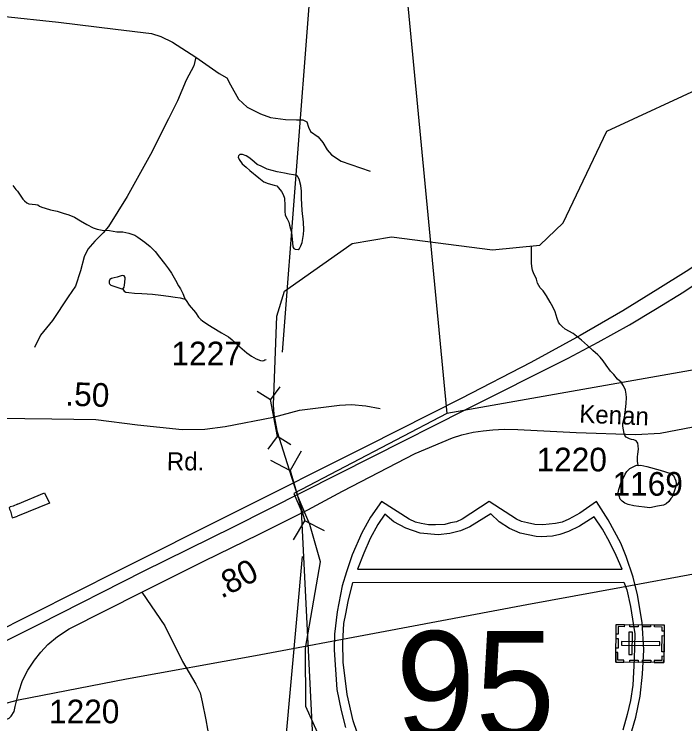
# Model space of a CAD drawing. Extents: x 2082433 to 2279600, y 546599 to 755198.
# Drawn here: x 2149060 to 2152603, y 600142 to 603893 of the extents above; entities that cross this region are included whole.
import ezdxf

# ---------------------------------------------------------------- set-up
doc = ezdxf.new("R2010")
doc.units = 0
for name, color, linetype in [('Exist Boundary Political Fire Districts', 7, 'Continuous'), ('Exist Cultural Cemetery CELL', 7, 'Continuous'), ('Exist Hydrographic Creek Single Shore', 7, 'Continuous'), ('Exist Hydrographic Misc Water Feature', 7, 'Continuous'), ('Exist Hydrographic Pond Under 1500 Sq Ft', 7, 'Continuous'), ('Exist Road Non-System Type 51', 7, 'Continuous'), ('Exist Road Primary Interstate Divided Center Attributed', 7, 'Continuous'), ('Exist Road Primary Interstate Shield CELL', 7, 'Continuous'), ('Exist Road Primary Interstate Shield Number Label', 7, 'Continuous'), ('Exist Road Primary Interstate Structure Culvert CELL', 7, 'Continuous'), ('Exist Road Primary Interstate Structure Culvert Number Label', 7, 'Continuous'), ('Exist Road Secondary Mileage Hundredths English Label', 7, 'Continuous'), ('Exist Road Secondary Structure Culvert CELL', 7, 'Continuous'), ('Exist Road Secondary Structure Standard Bridge Number Label', 7, 'Continuous'), ('Exist Road Secondary Type 51 Attributed', 7, 'Continuous'), ('Exist Road Secondary Type 51 Label', 7, 'Continuous'), ('Exist Road Secondary Type 51 Number Label', 7, 'Continuous'), ('Exist Utilities Electrical Transmission Line', 7, 'Continuous')]:
    doc.layers.add(name, color=color, linetype=linetype)

msp = doc.modelspace()

# ---------------------------------------------------------------- linework, layer by layer
at = {"layer": 'Exist Boundary Political Fire Districts'}
for points in [[(2150227.4, 608573.5), (2150803.4, 607458.3), (2151346, 601782.1)], [(2159905.3, 603293.7), (2151346, 601782.1)], [(2151346, 601782.1), (2150536.8, 601359.3), (2150575.6, 601269.6), (2150804, 596727.4), (2150538.7, 590463.1), (2150181.1, 589645.7), (2149537.2, 589006.2), (2148987.7, 588267)]]:
    msp.add_lwpolyline(points, dxfattribs=at)
at = {"layer": 'Exist Cultural Cemetery CELL'}
for points in [[(2152238.3, 600467.9), (2152240.1, 600667), (2152494.7, 600664.7), (2152492.9, 600465.6)], [(2152283.5, 600666.7), (2152283.4, 600655.3), (2152251.2, 600655.6), (2152250.8, 600615.1), (2152239.7, 600615.2), (2152240.2, 600667.1)], [(2152356.5, 600654.6), (2152313.1, 600655), (2152313.2, 600666.4), (2152356.6, 600666)], [(2152422.4, 600654), (2152379.1, 600654.4), (2152379.2, 600665.7), (2152422.5, 600665.4)], [(2152494.4, 600631.5), (2152483, 600631.6), (2152483.2, 600653.6), (2152442.7, 600654), (2152442.8, 600665.1), (2152494.7, 600664.7)], [(2152306.7, 600508.1), (2152325.4, 600507.9), (2152326.5, 600625.7), (2152307.8, 600625.9)], [(2152482, 600523.2), (2152482.7, 600608), (2152494.1, 600607.9), (2152493.4, 600523)], [(2152239, 600542), (2152239.5, 600593.8), (2152250.9, 600593.7), (2152250.4, 600541.9)], [(2152268.6, 600576.7), (2152268.4, 600558), (2152471.2, 600556.1), (2152471.4, 600574.8)], [(2152281.6, 600467.5), (2152281.7, 600478.9), (2152249.5, 600479.2), (2152249.9, 600519.7), (2152238.8, 600519.8), (2152238.3, 600467.9)], [(2152493.2, 600498.7), (2152481.7, 600498.8), (2152481.5, 600476.8), (2152441.1, 600477.1), (2152441, 600466), (2152492.9, 600465.5)], [(2152355.8, 600466.8), (2152312.4, 600467.2), (2152312.6, 600478.6), (2152355.9, 600478.2)], [(2152423, 600466.2), (2152379.7, 600466.6), (2152379.8, 600478), (2152423.1, 600477.6)]]:
    msp.add_lwpolyline(points, close=True, dxfattribs=at)
at = {"layer": 'Exist Hydrographic Creek Single Shore'}
for points in [[(2150737.1, 599557.9), (2150812.2, 599625.3), (2150811.2, 599766.4), (2150600.2, 600233.2), (2150599.1, 600541.6), (2150679.1, 600999.1), (2150621.9, 601196.4), (2150595.1, 601256.7), (2150558.2, 601345.6), (2150514.5, 601483.1), (2150451, 601683.5), (2150434.2, 601777.4), (2150430.8, 601828.1), (2150447.2, 602296.3), (2150488.2, 602430), (2150845.2, 602681.9), (2151053.1, 602717.1), (2151586.3, 602647.2), (2151836.2, 602671.7), (2151960.3, 602790.6), (2152191.2, 603274.7), (2152731.3, 603526.1)], [(2152357.1, 601507.5), (2152352.8, 601531.2), (2152353, 601539.3), (2152352.8, 601553.6), (2152354.6, 601567.4), (2152358.5, 601593.2), (2152356.5, 601611.4), (2152354.2, 601625.5), (2152350.5, 601631.4), (2152346.2, 601637.3), (2152334.1, 601643.2), (2152322.2, 601645.4), (2152310.1, 601649.2), (2152300.1, 601653.2), (2152292.3, 601657.2), (2152286.1, 601667), (2152282, 601677), (2152275.9, 601714.8), (2152275.7, 601729), (2152281.6, 601748.8), (2152285.5, 601773), (2152289.2, 601802.8), (2152292.9, 601835.1), (2152294.9, 601866.9), (2152292.7, 601885), (2152288.8, 601906.7), (2152278.3, 601929), (2152266.4, 601948.6), (2152248.2, 601964.7), (2152228.5, 601988.4), (2152210.3, 602006.6), (2152188.3, 602038.3), (2152171.5, 602060.3), (2152155.7, 602080.1), (2152143.6, 602092.1), (2152117.4, 602115.9), (2152089.5, 602141.6), (2152057.1, 602169.6), (2152031.5, 602191.4), (2152012.8, 602205.2), (2151971, 602228.9), (2151954.6, 602242.7), (2151942.9, 602254.6), (2151936.5, 602264.9), (2151928.7, 602284.8), (2151918.7, 602320.8), (2151906.4, 602346.5), (2151892, 602370.6), (2151872.3, 602404.4), (2151854.1, 602430.3), (2151839.7, 602446.3), (2151831.7, 602460), (2151825.6, 602471.9), (2151819.6, 602491.9), (2151815.3, 602501.9), (2151805.3, 602520), (2151799.1, 602540), (2151795.2, 602560.1), (2151793, 602579.8), (2151792.2, 602667.4)]]:
    msp.add_lwpolyline(points, dxfattribs=at)
at = {"layer": 'Exist Hydrographic Misc Water Feature'}
for points in [[(2150304.5, 603067.3), (2150353.1, 603027.5), (2150378.7, 603007.8), (2150401.3, 602997.9), (2150433.3, 602990.3), (2150447, 602986.2), (2150457.3, 602976.1), (2150473.1, 602956.3), (2150481.5, 602940.4), (2150487.4, 602920.4), (2150489.7, 602882.3), (2150489.9, 602850.3), (2150491.9, 602832.5), (2150494, 602826.6), (2150502.2, 602812.3), (2150510.4, 602794.5), (2150514.5, 602778.4), (2150524.3, 602738.8), (2150530.7, 602686.8), (2150532.9, 602662.9), (2150537.2, 602654.9), (2150545, 602650.9), (2150560.8, 602648.9), (2150567, 602654.9), (2150574.8, 602669.1), (2150580.7, 602686.9), (2150588.7, 602729.1), (2150590.6, 602753.2), (2150588.3, 602793.2), (2150581.9, 602855), (2150577.2, 602921), (2150577.4, 602957.1), (2150575.2, 602987), (2150564.9, 603020.6), (2150559, 603032.9), (2150556.7, 603036.9), (2150552.6, 603040.7), (2150536.6, 603044.7), (2150512.6, 603048.4), (2150488.6, 603052.4), (2150448.7, 603060.1), (2150396.6, 603074.1), (2150364.8, 603089.8), (2150344.3, 603099.4), (2150314.8, 603123.3), (2150300.6, 603135.2), (2150286.1, 603145.1), (2150266.2, 603151), (2150252.2, 603151.1), (2150244.4, 603144.9), (2150244.2, 603136.8), (2150248.7, 603124.8), (2150264.5, 603102.9), (2150285, 603085.2), (2150304.5, 603067.3)], [(2149053.5, 602987.6), (2149069.5, 602966.5)], [(2149069.5, 602966.5), (2149077.5, 602958.4), (2149106, 602914.7), (2149114, 602906.6), (2149126.3, 602896.7), (2149138.2, 602890.9), (2149156, 602889), (2149172.4, 602886.9), (2149184.3, 602885.1), (2149193.9, 602879.2), (2149206.2, 602873.3), (2149224.3, 602867.3), (2149252.4, 602859.4), (2149286.4, 602851.8), (2149318.2, 602841.7), (2149348.6, 602831.9), (2149378.5, 602820.1), (2149410.3, 602800.2), (2149444.7, 602782.4), (2149476.7, 602764.6), (2149498.9, 602756.8), (2149524.5, 602750.9), (2149563, 602749.2), (2149602.8, 602743.5), (2149634.8, 602743.6), (2149665, 602735.8), (2149696.7, 602726), (2149713.1, 602714.3), (2149750.9, 602688.3), (2149779.2, 602664.5), (2149805.6, 602638.6), (2149827.8, 602608.9), (2149854, 602575), (2149875.7, 602546.9), (2149891.9, 602525), (2149912, 602487.5), (2149928.4, 602457.5), (2149938.5, 602441.3), (2149950.6, 602417.6), (2149960.6, 602393.8), (2149962.5, 602389.5)], [(2149633.6, 602440.2), (2149640.5, 602449.9), (2149642.6, 602461.7), (2149646.3, 602493.6), (2149646.3, 602501.7), (2149642, 602509.7), (2149630.1, 602511.9), (2149604.1, 602503.7), (2149588.1, 602499.6), (2149574.3, 602495.6), (2149566.3, 602491.5), (2149564.5, 602487.4), (2149562, 602481.2), (2149562.4, 602477.5), (2149562.6, 602471.4), (2149564.5, 602467.5), (2149570.2, 602461.3), (2149633.6, 602440.2)], [(2149633.6, 602440.2), (2149640.5, 602429.6), (2149650.8, 602424), (2149665, 602421.8), (2149694.9, 602418.2), (2149734.5, 602416.2), (2149790.9, 602412.6), (2149834.7, 602408.7), (2149874.7, 602403.1), (2149910.6, 602397.3), (2149936.9, 602393.3), (2149956.5, 602389.5), (2149962.5, 602389.5)], [(2149962.5, 602389.5), (2149969, 602379.6), (2149985, 602355.6), (2150017.4, 602315.8), (2150033.4, 602291.9), (2150045.5, 602280), (2150055.2, 602272), (2150077.7, 602256.4), (2150105.6, 602238.4), (2150156.1, 602208.9), (2150191.9, 602186.9), (2150212.2, 602171.2), (2150252.2, 602135.2), (2150288.5, 602103.7), (2150314.4, 602085.6), (2150338.5, 602071.8), (2150360.7, 602062), (2150370.5, 602060.1), (2150378.5, 602062.1), (2150384.3, 602066.1), (2150390.6, 602068)], [(2149077.3, 601303.4), (2149220.8, 601363.6), (2149247.3, 601308.1), (2149077.7, 601239.7)], [(2149077.3, 601303.4), (2149055.5, 601293.3), (2149039.5, 601289.2), (2149033.6, 601283.2), (2149035.4, 601277.3), (2149040, 601265.3), (2149043.4, 601251.4), (2149047.5, 601237.4), (2149050, 601231.3), (2149061.7, 601233.6), (2149077.7, 601239.7)]]:
    msp.add_lwpolyline(points, dxfattribs=at)
at = {"layer": 'Exist Hydrographic Pond Under 1500 Sq Ft'}
msp.add_lwpolyline([(2152357.1, 601507.5), (2152370.8, 601509.4), (2152403.2, 601501.7), (2152473.1, 601482.2), (2152529.1, 601464.4), (2152543.3, 601454.6), (2152555.2, 601426.4), (2152557.2, 601410.7), (2152553.5, 601390.6), (2152547.6, 601370.8), (2152535.7, 601340.6), (2152529.7, 601332.5), (2152518, 601316.5), (2152504.3, 601304.4), (2152490, 601298.4), (2152458, 601292.3), (2152418.4, 601284.1), (2152390.1, 601287.6), (2152360.2, 601291.7), (2152333.9, 601295.2), (2152304, 601301.4), (2152286.1, 601308.9), (2152272, 601319.2), (2152261.7, 601328.8), (2152255.8, 601346.8), (2152251.7, 601362.8), (2152253.7, 601380.7), (2152265.4, 601415), (2152287.2, 601461.2), (2152297.2, 601475.2), (2152313, 601491), (2152330.8, 601501.3), (2152347, 601509.4), (2152357.1, 601507.5)], dxfattribs=at)
at = {"layer": 'Exist Road Non-System Type 51'}
for points in [[(2148996, 603882.5), (2149294.2, 603851.8), (2149595.7, 603814.2), (2149785.4, 603792), (2149834.9, 603774.9), (2149896.5, 603745.8), (2150019.5, 603665.5)], [(2150019.5, 603665.5), (2150009.2, 603621.1), (2149968.2, 603544.2), (2149923.8, 603434.9), (2149875.9, 603340.9), (2149781.1, 603151.2), (2149656.4, 602929.1), (2149558.1, 602771.9), (2149530.8, 602737.7), (2149486.4, 602693.3), (2149448.8, 602650.6), (2149430, 602611.3), (2149410.3, 602536.1), (2149384.7, 602455.8), (2149345.4, 602399.4), (2149261.7, 602274.7), (2149199.3, 602196.1), (2149166.9, 602131.2)], [(2150019.5, 603665.5), (2150143.3, 603580.1), (2150184.4, 603556.2), (2150203.1, 603520.3), (2150245.9, 603443.4), (2150290.3, 603402.4), (2150362.1, 603366.5), (2150415, 603347.7), (2150493.6, 603337.5), (2150551.7, 603334.1), (2150585, 603334.1), (2150605.5, 603323.8), (2150615.8, 603296.5), (2150626, 603272.5), (2150665.3, 603245.2), (2150691, 603214.5), (2150713.2, 603176.9), (2150737.1, 603149.5), (2150788.4, 603117.1), (2150940.4, 603064.1)], [(2149733.9, 600838), (2149855.9, 600660.4), (2149948.9, 600472), (2150019.2, 600350.7), (2150042.5, 600305.5), (2150052.8, 600259), (2150072.1, 600162.2), (2150089.6, 600064.1)]]:
    msp.add_lwpolyline(points, dxfattribs=at)
at = {"layer": 'Exist Road Primary Interstate Divided Center Attributed'}
for points in [[(2154005.8, 603556), (2153907.2, 603479.9), (2153476.1, 603147), (2152986.5, 602780.6), (2152609.7, 602532.4), (2152461.1, 602439.2), (2152275.6, 602325.8), (2152050.1, 602194.5), (2151789.6, 602051.5), (2151421, 601862.5), (2150923, 601610.5), (2150213.3, 601253.1), (2149606, 600948.8), (2148933.1, 600610.7)], [(2148940.2, 600543.8), (2149196, 600671.3), (2149743.3, 600948.3), (2150217.9, 601183.8), (2150954.5, 601555), (2151443.2, 601802.7), (2151985.9, 602075.4), (2152145.7, 602160.2), (2152309.9, 602250.8), (2152448.2, 602333.3), (2152597.5, 602425.6), (2152774.6, 602544.2), (2152989.1, 602697), (2153314.4, 602944.9), (2153689.9, 603233.2), (2154026.9, 603492.9)]]:
    msp.add_lwpolyline(points, dxfattribs=at)
at = {"layer": 'Exist Road Primary Interstate Shield CELL'}
for points in [[(2152310.3, 600063.4), (2152344.8, 600177.8), (2152367.7, 600288.8), (2152379.3, 600404.4), (2152387, 600532.6), (2152378.3, 600677), (2152353.2, 600824.6), (2152329.6, 600916.4), (2152293.9, 601026.4), (2152264.7, 601096.6), (2152197.2, 601221.2), (2152136.5, 601317.1), (2152048.3, 601255), (2151990.7, 601224.4), (2151955.6, 601208.6), (2151919.4, 601201.5), (2151853, 601193.5), (2151811.3, 601195.3), (2151772.6, 601204.1), (2151739.8, 601211.2), (2151713.1, 601224.4), (2151569.8, 601317.1), (2151426.3, 601224.4), (2151396.2, 601210.6), (2151365.4, 601204.1), (2151335.8, 601195.9), (2151286.7, 601193.5), (2151249.2, 601194.7), (2151210.8, 601201.5), (2151180.4, 601207.9), (2151146.3, 601224.4), (2151000.2, 601317.1), (2150942.7, 601233.8), (2150895.9, 601151.4), (2150846.1, 601035), (2150815.2, 600944.9), (2150793.1, 600870.7), (2150766, 600734.8), (2150752.1, 600616.4), (2150749.7, 600532.6), (2150765, 600323.6), (2150787.8, 600212.3), (2150811.3, 600122.3)], [(2150895.1, 600028.4), (2150851.5, 600157.7), (2150819.8, 600297.3), (2150798.4, 600467.8), (2150796, 600571.7), (2150802.3, 600671.6), (2150811.9, 600724), (2150824.5, 600789), (2150850, 600889.4), (2152281, 600890.1), (2152296, 600850.6), (2152316.6, 600762.9), (2152327.4, 600695.4), (2152338.5, 600617.7), (2152334.6, 600484.4), (2152328.2, 600346.5), (2152315.5, 600264.8), (2152298.5, 600190.5), (2152275.3, 600108)]]:
    msp.add_lwpolyline(points, dxfattribs=at)
msp.add_lwpolyline([(2151017.6, 601249.8), (2150982, 601195), (2150940.9, 601121), (2150908, 601044.3), (2150874.5, 600959.6), (2152272.7, 600959.1), (2152240.2, 601031.7), (2152205.3, 601104.7), (2152168.8, 601171.3), (2152124.4, 601235.8), (2152046, 601186.4), (2151988.9, 601159.4), (2151942.9, 601143.6), (2151904.1, 601134.8), (2151843.9, 601130.1), (2151816.9, 601131.7), (2151732.9, 601150.7), (2151676, 601173.9), (2151621.9, 601210), (2151578.1, 601251.3), (2151467.3, 601184.2), (2151418.2, 601162.6), (2151361.7, 601148.1), (2151299.8, 601140.4), (2151204.5, 601150.7), (2151129.7, 601176.5), (2151065.3, 601210)], close=True, dxfattribs=at)
at = {"layer": 'Exist Road Primary Interstate Structure Culvert CELL'}
for p, q in [((2150576.6, 601582.7), (2150517.7, 601482)), ((2150414, 601535.4), (2150517.7, 601482)), ((2150517.7, 601482), (2150595.3, 601215.4)), ((2150536.4, 601114.7), (2150595.3, 601215.4)), ((2150699, 601162), (2150595.3, 601215.4))]:
    msp.add_line(p, q, dxfattribs=at)
at = {"layer": 'Exist Road Primary Interstate Structure Culvert Number Label'}
msp.add_line((2150581.7, 601026.7), (2150355.7, 598540.5), dxfattribs=at)
at = {"layer": 'Exist Road Secondary Structure Culvert CELL'}
for p, q in [((2150463.2, 601923.7), (2150414.4, 601856.2)), ((2150344.3, 601901.2), (2150414.4, 601856.2)), ((2150451.3, 601661.3), (2150414.4, 601856.2)), ((2150402.5, 601593.8), (2150451.3, 601661.3)), ((2150521.4, 601616.2), (2150451.3, 601661.3))]:
    msp.add_line(p, q, dxfattribs=at)
at = {"layer": 'Exist Road Secondary Structure Standard Bridge Number Label'}
msp.add_line((2150477, 602106.8), (2150628, 604070.4), dxfattribs=at)
at = {"layer": 'Exist Road Secondary Type 51 Attributed'}
for points in [[(2150429.7, 601763.7), (2150568.3, 601800.8), (2150778.3, 601826.1), (2150842.5, 601829.6), (2150918, 601823.8), (2150994.2, 601808.3)], [(2148557.5, 601633.6), (2148739.7, 601716), (2148853.2, 601745.2), (2148971.8, 601757.6), (2149259.9, 601754.5), (2149490.9, 601749.9), (2149711.2, 601722.1), (2149948.4, 601697.5), (2150066.6, 601698.8), (2150175.5, 601712.9), (2150429.7, 601763.7)], [(2150611.7, 601273.5), (2150794.4, 601372.5), (2151178.7, 601570.7), (2151375.9, 601654.3), (2151425.3, 601669.2), (2151485.2, 601684.2), (2151536.9, 601691.7), (2151588.7, 601696.3), (2151648.1, 601699), (2151720.1, 601698.4), (2152029.7, 601682.9), (2152344.1, 601672.3), (2152473.5, 601678.2), (2152646.9, 601711.4)], [(2148945.3, 600159.5), (2148974.6, 600157.6), (2149004.2, 600160), (2149021.5, 600166), (2149033.5, 600172.1), (2149044.7, 600182), (2149060, 600206.5), (2149066, 600234.2), (2149084, 600310.5), (2149104.7, 600371.3), (2149132.4, 600426), (2149167.1, 600479.1), (2149200.2, 600521.5), (2149238.7, 600561.5), (2149289.5, 600603.9), (2149351.1, 600644.7), (2149733.9, 600838), (2150062.3, 601002.1), (2150354.2, 601144.5), (2150611.7, 601273.5)]]:
    msp.add_lwpolyline(points, dxfattribs=at)
at = {"layer": 'Exist Utilities Electrical Transmission Line'}
msp.add_lwpolyline([(2146173.6, 599684.5), (2146621.1, 599768.4), (2147064.7, 599848.2), (2147516, 599936.3), (2148003.5, 600022.4), (2148508.9, 600114.5), (2148895.3, 600219.8), (2149083, 600268.3), (2149654.2, 600379.5), (2150335.4, 600503.3), (2150992.4, 600626.9), (2151769.2, 600773.3), (2152268.6, 600864), (2152668, 600938.2), (2153880.3, 601171), (2155131.4, 601955.6), (2156884.7, 603037.1), (2159164, 604449.3), (2161823.7, 606095.6)], dxfattribs=at)

# ---------------------------------------------------------------- texts
at = {"layer": 'Exist Road Primary Interstate Shield Number Label'}
msp.add_text('95', height=567, dxfattribs=at).set_placement((2151074.4, 600065))
at = {"layer": 'Exist Road Secondary Mileage Hundredths English Label'}
for s, rotation, p in [('.50', 358.0683, (2149328.9, 601824.4)), ('.80', 27.4997, (2150154.9, 600802.1))]:
    msp.add_text(s, height=125, rotation=rotation, dxfattribs=at).set_placement(p)
at = {"layer": 'Exist Road Secondary Type 51 Label'}
for s, rotation, p in [('Kenan', 357.632, (2152044, 601734.4)), ('Rd.', 359.726, (2149866.5, 601482.3))]:
    msp.add_text(s, height=95, rotation=rotation, dxfattribs=at).set_placement(p)
at = {"layer": 'Exist Road Secondary Type 51 Number Label'}
for s, p in [('1227', (2149890.9, 602037.1)), ('1220', (2151819.6, 601476.5)), ('1169', (2152221, 601348)), ('1220', (2149244.2, 600144.7))]:
    msp.add_text(s, height=125, dxfattribs=at).set_placement(p)

doc.saveas('drawing.dxf')
